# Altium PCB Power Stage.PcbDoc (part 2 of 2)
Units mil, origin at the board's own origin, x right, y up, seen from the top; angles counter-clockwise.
Board outline 9000 x 8000 mil, 6 copper layers (Top Layer, Layer 1, Layer 2, Layer 3, Layer 4, Bottom Layer), stack 92.2 mil thick; 168 components, 72 nets, 534 pads, 347 vias.
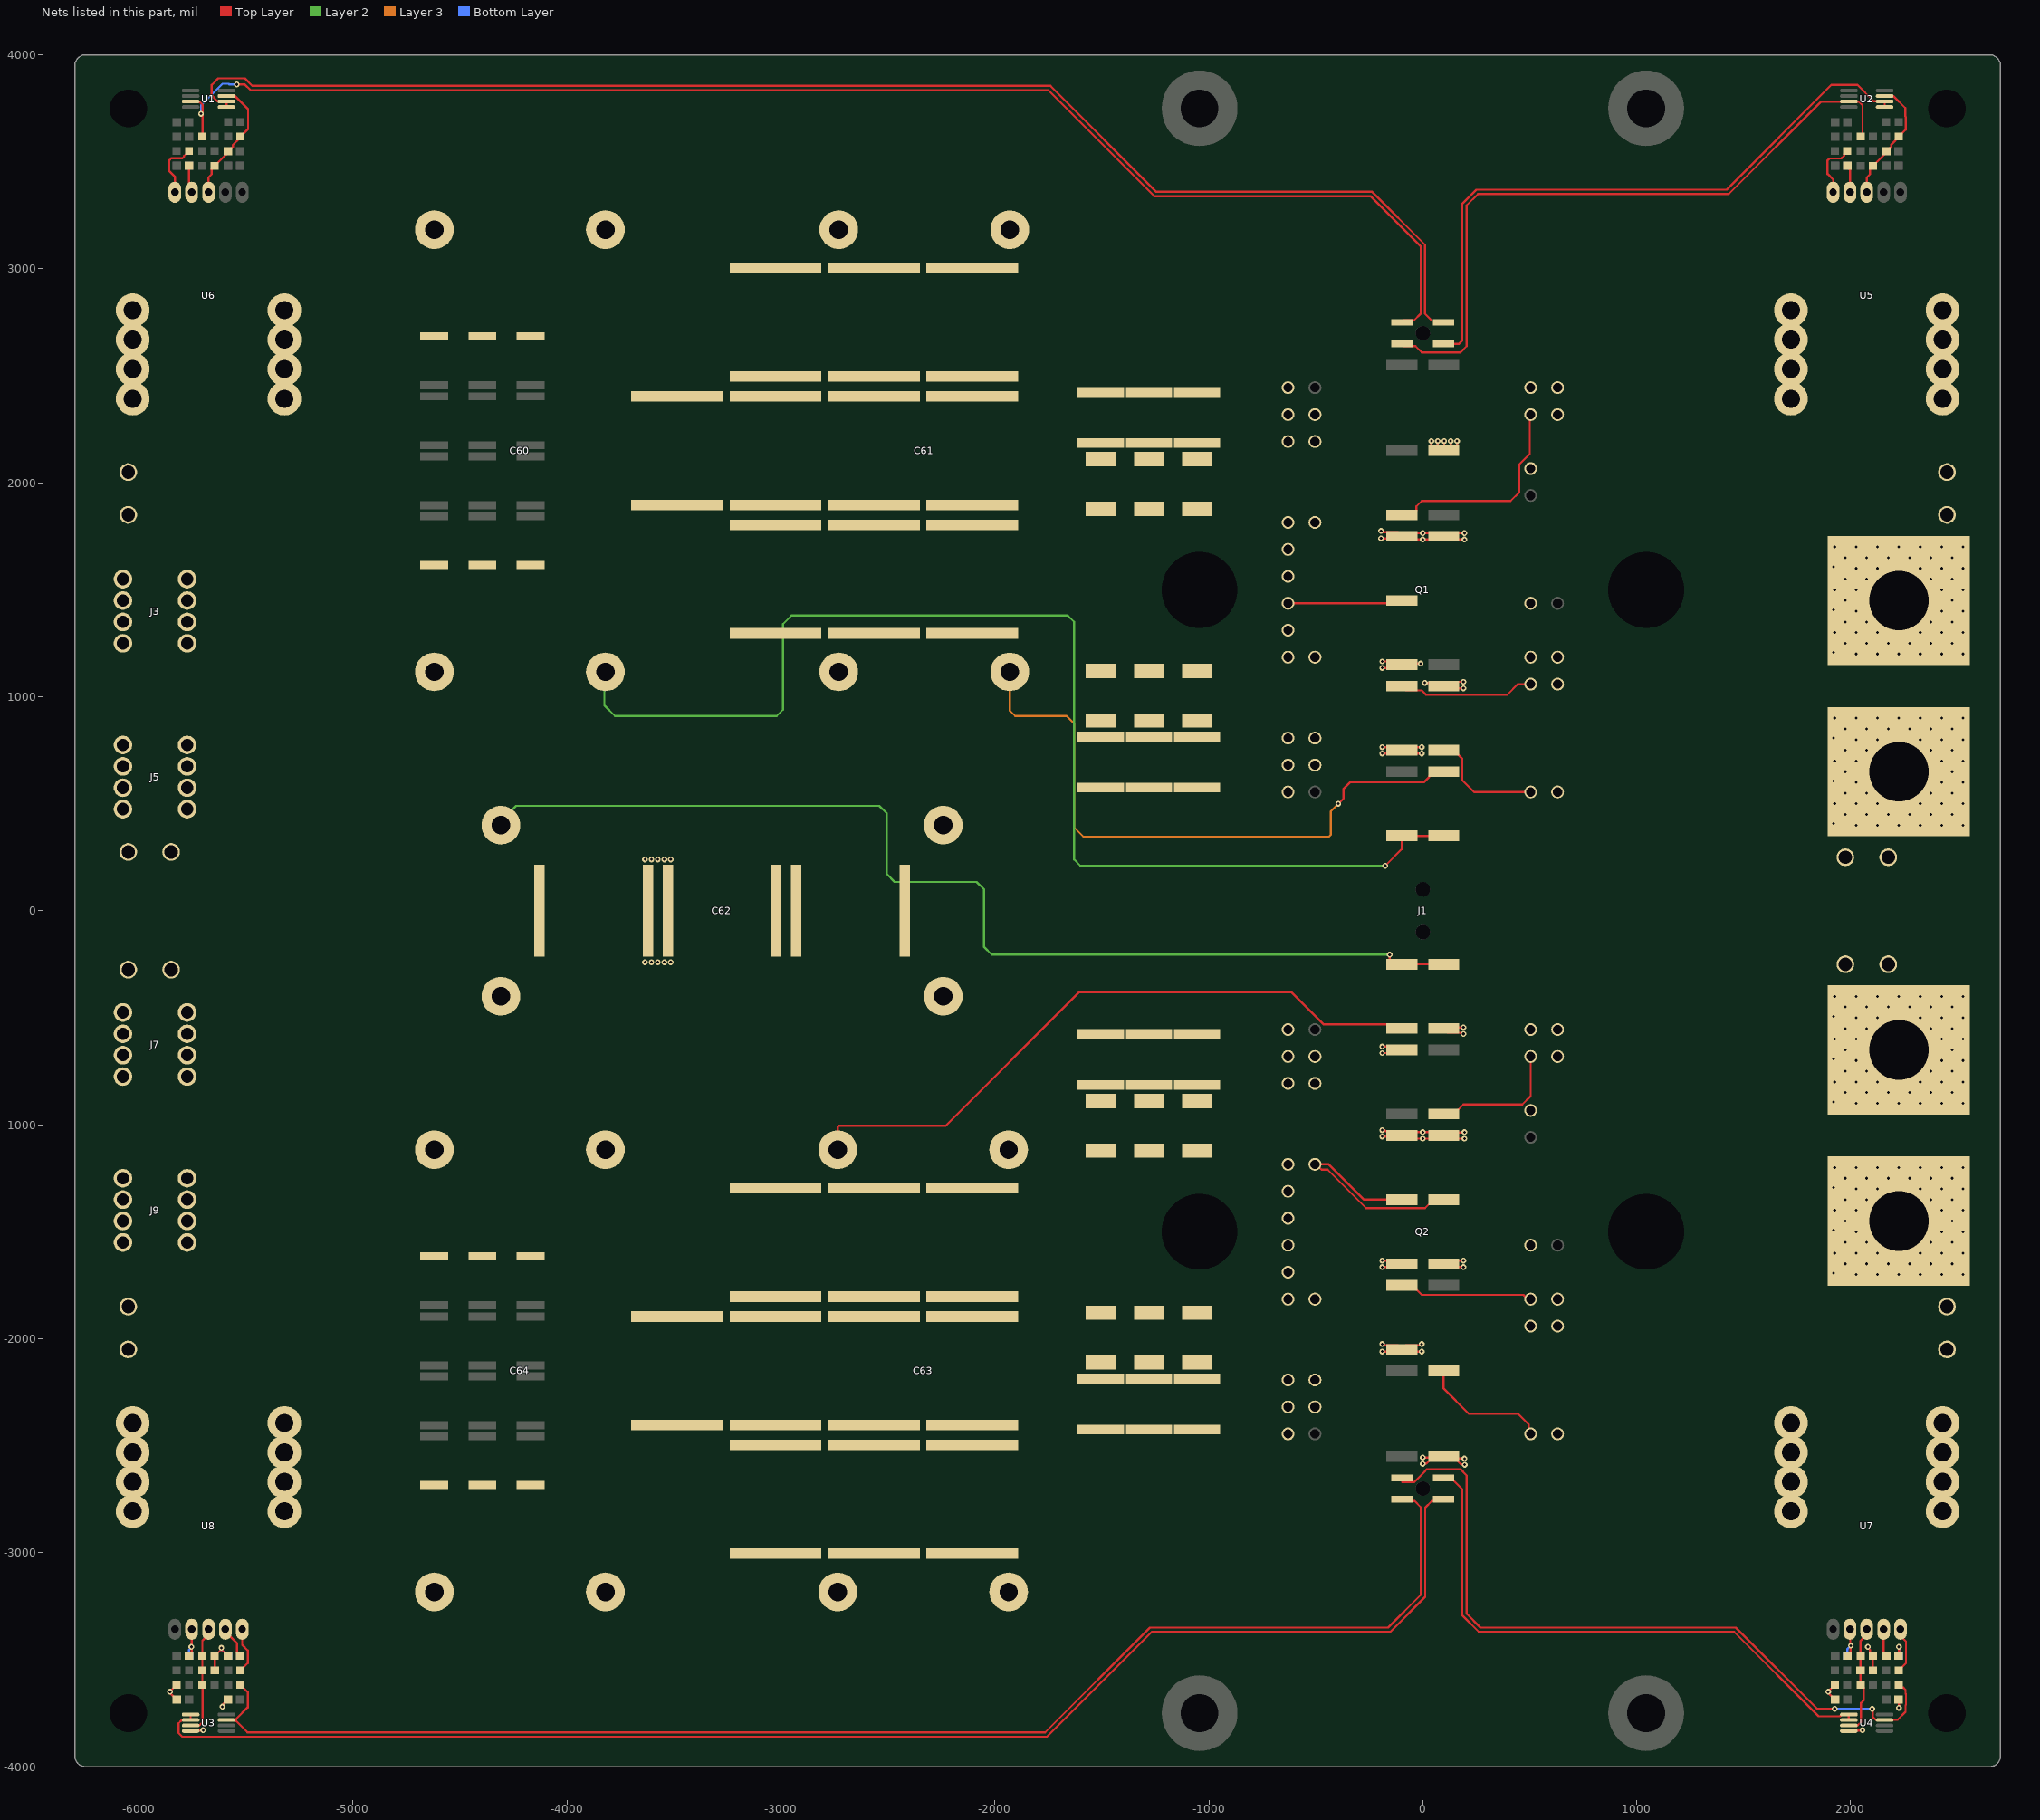
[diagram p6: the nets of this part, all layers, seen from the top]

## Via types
v1: diameter 27, hole 13, Top Layer to Bottom Layer, tented both sides, 347 vias

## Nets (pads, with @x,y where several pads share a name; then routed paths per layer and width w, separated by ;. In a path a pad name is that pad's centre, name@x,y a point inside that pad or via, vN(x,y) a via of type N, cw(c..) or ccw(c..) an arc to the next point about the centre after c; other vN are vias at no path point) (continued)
GND_S: C46.2 C47.2 C48.2 C49.2 C50.2 C51.2 C52.2 C53.2 C54.2 C55.2 C65.2 C66.2 C67.2 C68.2 J1.108 R49.1 R50.1 R55.1 R58.1 U3.4 U4.4 U7.2 U8.2 | length 1529.4
  Top Layer w10: C52.2@-5823.58,-3686 -5824.53,-3686 -5851.75,-3658.78 -5851.75,-3653.25 v1(-5855,-3650) -5855,-3648.47 -5824.53,-3618 R55.1@-5823.62,-3618 ; C46.2@-5766.42,-3482 -5753.74,-3469.32 U8.2@-5753.74,-3357.87 ; U3.4@-5758.66,-3833.39 -5757.18,-3831.91 -5701.91,-3831.91 v1(-5700,-3830) ; C50.2@-5646.42,-3550 -5645.47,-3549.05 -5645.47,-3482 v1@-5618.25,-3454.78 ; v1@-5611.75,-3454.78 -5584.53,-3482 C47.2@-5583.58,-3482 ; v1(-5610,-3720) -5606.75,-3716.75 -5606.75,-3708.22 -5584.53,-3686 C53.2@-5583.58,-3686 ; v1(0,-2585) 1.5,-2583.5 16.5,-2583.5 50,-2550 J1.108@97.44,-2550 107.44,-2560 v1(195,-2560) ; v1(0,-2555) J1.108@87.56,-2555 ; J1.108@145.67,-2554.29 179.17,-2587.79 v1@194.17,-2587.79 ; C54.2@1926.42,-3686 1925.47,-3686 1898.25,-3658.78 1898.25,-3653.25 v1(1895,-3650) 1895,-3648.47 1925.47,-3618 R58.1@1926.38,-3618 ; C48.2@1983.58,-3482 1984.53,-3482 1998.39,-3468.14 1998.39,-3436.61 v1(2000,-3435) 1998.13,-3433.13 1998.13,-3359.74 U7.2@1996.26,-3357.87 ; U4.4@1991.34,-3833.39 1992.82,-3831.91 2053.09,-3831.91 v1(2055,-3830) ; v1(2080,-3440) 2080,-3444.6 2089.76,-3454.36 2089.76,-3469.04 2102.72,-3482 R50.1@2103.62,-3482 R50.1@2103.62,-3482 C51.2@2103.58,-3550 ; C55.2@2223.58,-3686 2225,-3687.42 v1(2225,-3725) ; C49.2@2223.58,-3482 2225,-3480.58 v1(2225,-3440)
  Bottom Layer w10: C68.2@-5766.42,-3482 -5766.42,-3453.71 -5755,-3442.29 v1(-5755,-3440) ; v1(-5615,-3445) -5611.75,-3448.25 -5611.75,-3454.78 -5584.53,-3482 C67.2@-5583.58,-3482 ; C66.2@1983.58,-3482 1983.58,-3451.42 v1(2000,-3435) ; C65.2@2223.58,-3482 2225,-3480.58 v1(2225,-3440)
  other v1: 195.67,-2589.29
IAC+_P: J1.004 U2.1 U2.2 | length 2995.4
  Top Layer w10: J1.004@97.44,2650 169.88,2650 185,2665.12 185,3305 250,3370 1420,3370 1910.41,3860.41 2030.54,3860.41 2107.26,3783.68 2157.18,3783.68 U2.2@2158.66,3782.2 U2.1@2158.66,3756.61
IAC+_S: J1.110 U4.1 U4.2 | length 2729.9
  Top Layer w10: J1.110@97.44,-2650 130.91,-2650 185,-2704.09 185,-3168.28 185,-3293.28 261.72,-3370 1455,-3370 1850,-3765 1949.14,-3765 1957.53,-3756.61 U4.1@1991.34,-3756.61 U4.2@1991.34,-3782.2
IAC-_P: J1.003 R5.1 U2.7 | length 3197.6
  Top Layer w10: J1.003@-97.44,2650 -86.69,2639.25 -34.25,2639.25 -5,2610 176.09,2610 205,2638.91 205,3296.72 258.28,3350 1430,3350 1862.2,3782.2 U2.7@1991.34,3782.2 1992.82,3780.73 2039.27,3780.73 2055,3765 2055,3626.62 R5.1@2046.38,3618
IAC-_S: J1.109 R60.1 U4.7 | length 3423.3
  Top Layer w10: -95,-2670 -40,-2670 10,-2620 10,-2618.79 18.79,-2610 176.09,-2610 205,-2638.9 205,-3285 270,-3350 1463.28,-3350 1843.28,-3730 v1(1925,-3730) ; v1(2100,-3730) 2102.32,-3732.32 2102.32,-3766.5 2116.55,-3780.73 2157.18,-3780.73 U4.7@2158.66,-3782.2 2160.14,-3780.73 2219.27,-3780.73 2256.28,-3743.72 2256.28,-3713.19 2258.39,-3711.08 2258.39,-3660.92 2256.28,-3658.81 2256.28,-3641.28 2245.96,-3630.96 2236.58,-3630.96 R60.1@2223.62,-3618
  Bottom Layer w10: v1(1925,-3730) v1(2100,-3730)
IDC+_P: J1.002 U1.1 U1.2 | length 6526.7
  Top Layer w10: U1.1@-5591.34,3756.61 U1.2@-5591.34,3782.2 -5592.82,3783.68 -5633.45,3783.68 -5660,3810.24 -5660,3860 -5629.61,3890.39 -5505.39,3890.39 -5470,3855 -1740,3855 -1245,3360 -236.72,3360 10,3113.28 10,2790 40.63,2759.37
IDC+_S: J1.112 U3.1 U3.2 | length 6757.6
  Top Layer w10: U3.1@-5758.66,-3756.61 U3.2@-5758.66,-3782.2 -5760.14,-3783.68 -5800.77,-3783.68 -5815,-3797.91 -5815,-3843.27 -5798.27,-3860 -1756.72,-3860 -1266.72,-3370 -152.17,-3370 11.04,-3206.79 11.04,-2789.14 41.69,-2758.49 61.51,-2758.49 70,-2750 J1.112@97.44,-2750
IDC-_P: J1.001 R3.1 U1.7 | length 6727.4
  Top Layer w10: U1.7@-5758.66,3782.2 -5757.18,3780.73 -5716.55,3780.73 -5702.32,3766.5 -5702.32,3619.3 R3.1@-5703.62,3618 ; v1(-5542.84,3861.89) -5542.45,3861.5 -5504.78,3861.5 -5478.28,3835 -1750,3835 -1255,3340 -245,3340 -10,3105 -10,2790 -40.63,2759.37 -88.07,2759.37 J1.001@-97.44,2750
  Bottom Layer w10: v1(-5710,3725) -5710,3765 -5610,3865 -5580.47,3865 -5576.97,3861.5 -5543.22,3861.5 v1(-5542.84,3861.89)
IDC-_S: J1.111 R57.1 U3.7 | length 6545.3
  Top Layer w10: R57.1@-5526.38,-3618 -5525.47,-3618 -5491.61,-3651.86 -5491.61,-3723.11 -5546.57,-3778.06 -5546.57,-3786.35 -5492.91,-3840 -1765,-3840 -1275,-3350 -162.17,-3350 -8.96,-3196.79 -8.96,-2788.06 -37.93,-2759.09 -88.35,-2759.09 J1.111@-97.44,-2750
NTC_P: J1.042 Q1.NTC1 | length 545.7
  Top Layer w10: J1.042@97.44,750 144.88,750 184.88,710 184.88,610.12 239.88,555.12 Q1.NTC1@503.94,555.12
NTC_S: J1.100 Q2.NTC1 | length 599.3
  Top Layer w10: J1.100@97.44,-2150 97.44,-2232.44 215,-2350 445,-2350 494.88,-2399.88 494.88,-2435.83 Q2.NTC1@503.94,-2444.88 Q2.NTC1@504.88,-2443.94
OCD_P_: R7.1 U6.5 | length 283.5
  Top Layer w10: U6.5@-5823.47,3366.88 U6.5@-5832.48,3357.87 -5832.48,3431.01 -5858.39,3456.92 -5858.39,3507.08 -5848.42,3517.04 -5798.55,3517.04 -5789.76,3525.83 -5789.76,3527.52 -5767.28,3550 R7.1@-5766.38,3550
OCD_PB: R9.1 U5.5 | length 272.1
  Top Layer w10: U5.5@1917.52,3357.87 1917.52,3417.48 1891.61,3443.39 1891.61,3507.08 1900.4,3515.86 1956.18,3515.86 1969.76,3529.45 1969.76,3537.04 1977.72,3545 R9.1@1983.62,3545
OCD_S-: R52.1 U8.5 | length 217.8
  Top Layer w10: R52.1@-5526.38,-3550 -5525.47,-3550 -5491.61,-3516.14 -5491.61,-3456.92 -5517.52,-3431.01 U8.5@-5517.52,-3357.87
OCD_SA: R54.1 U7.5 | length 217.8
  Top Layer w10: R54.1@2223.62,-3550 2224.53,-3550 2258.39,-3516.14 2258.39,-3414.62 2232.48,-3388.71 U7.5@2232.48,-3357.87
P+: C11.1 C12.1 C13.1 C17.1 C18.1 C19.1 C20.1 C21.1 C22.1 C23.1 C60.1A C60.1B C61.1A C61.1B J1.027 J1.049 J1.050 J5.1 J5.2 J5.3 J5.4 J5.5 J5.6 J5.7 J5.8 Q1.DC+_1 Q1.DC+_2 Q1.DC+_3 Q1.DC+_4 Q1.DC+_5 Q1.DC+_6 Q1.DC+_7 Q1.DC+_8 R19.2 R20.2 R21.2 R25.2 R26.2 R27.2 R28.2 R29.2 R30.2 TP5.1 TP6.1 | length 6297.3
  Top Layer w10: Q1.DC+_4@-629.92,1437.01 -110.43,1437.01 J1.027@-97.44,1450 ; v1(-176.01,210) -97.44,288.57 J1.049@-97.44,350 J1.050@97.44,350
  Layer 2 w10: C60.1A@-3820.39,1116.54 -3825,1111.93 -3825,960 -3775,910 -3020,910 -2990,940 -2990,1340 -2950,1380 -1660,1380 -1630,1350 -1630,240 -1600,210 v1(-176.01,210)
P-: C11.2 C12.2 C13.2 C14.2 C15.2 C16.2 C17.2 C18.2 C19.2 C20.2 C21.2 C22.2 C23.2 C24.2 C25.2 C26.2 C60.2A C60.2B C61.2A C61.2B J1.044 Q1.DC-1_1 Q1.DC-1_2 Q1.DC-1_3 Q1.DC-1_4 Q1.DC-2_1 Q1.DC-2_2 Q1.DC-2_3 Q1.DC-2_4 R13.1 R14.1 R15.1 U6.6 U6.7 U6.8 U6.9 | length 2957.7
  Top Layer w10: v1(-395,500) -370,525 -370,570 -340,600 5,600 30,625 30,630 50,650 J1.044@97.44,650
  Layer 3 w10: C61.2B@-1930.39,1116.54 -1930.39,935.39 -1905,910 -1665,910 -1630,875 -1630,390 -1585,345 -440,345 -430,355 -430,465 v1(-395,500)
P-_IO: J3.1 J3.2 J3.3 J3.4 J3.5 J3.6 J3.7 J3.8 TP1.1 TP3.1 U6.10 U6.11 U6.12 U6.13
PA: J1.035 J4.1 Q1.AC1_1 Q1.AC1_2 Q1.AC1_3 Q1.AC1_4 TP7.1 TP8.1 | length 638.3
  Top Layer w10: J1.035@-97.44,1050 -77.44,1030 -5,1030 15,1010 395,1010 444.06,1059.06 Q1.AC1_2@503.94,1059.06
  other v1: 2025,400 2125,400 2225,400 2325,400 2425,400 2525,400 1919.41,406.91 1975,450 2075,450 2175,450 2275,450 2375,450 2475,450 1925,500 2025,500 2125,500 2325,500 2425,500 2525,500 1975,550 2075,550 2375,550 2475,550 2025,600 2425,600 2525,600 1919.41,606.91 1975,650 2475,650 1925,700 2025,700 2425,700 2525,700 1975,750 2075,750 2375,750 2475,750 2025,800 2125,800 2325,800 2425,800 2525,800 1919.41,806.91 1975,850 2075,850 2175,850 2275,850 2375,850 2475,850 1925,900 2025,900 2125,900 2225,900 2325,900 2425,900 2525,900
PB: J1.019 Q1.AC2_1 Q1.AC2_2 Q1.AC2_3 Q1.AC2_4 U5.6 U5.7 U5.8 U5.9 | length 988.9
  Top Layer w10: J1.019@-97.44,1850 -50,1850 -30,1870 -30,1890 -5,1915 410,1915 450,1955 450,2085 500,2135 500,2314.96 Q1.AC2_2@503.94,2318.9
PB_IO: J2.1 TP2.1 TP4.1 U5.10 U5.11 U5.12 U5.13
  other v1: 2025,1200 2125,1200 2225,1200 2325,1200 2425,1200 2525,1200 1919.41,1206.91 1975,1250 2075,1250 2175,1250 2275,1250 2375,1250 2475,1250 1925,1300 2025,1300 2125,1300 2325,1300 2425,1300 2525,1300 1975,1350 2075,1350 2375,1350 2475,1350 2025,1400 2425,1400 2525,1400 1919.41,1406.91 1975,1450 2475,1450 1925,1500 2025,1500 2425,1500 2525,1500 1975,1550 2075,1550 2375,1550 2475,1550 2025,1600 2125,1600 2325,1600 2425,1600 2525,1600 1919.41,1606.91 1975,1650 2075,1650 2175,1650 2275,1650 2375,1650 2475,1650 1925,1700 2025,1700 2125,1700 2225,1700 2325,1700 2425,1700 2525,1700
S1_P: J1.033 J1.036 Q1.S1 | length 578.3
  Top Layer w10: v1(-190,1135) -112.44,1135 J1.033@-97.44,1150 ; v1(-190,1165) -112.44,1165 J1.033@-97.44,1150 ; v1(-10,1155) -92.44,1155 J1.033@-97.44,1150 ; v1(10,1065) 82.44,1065 J1.036@97.44,1050 ; v1(190,1040) 107.44,1040 J1.036@97.44,1050 ; v1(190,1070) 117.44,1070 J1.036@97.44,1050
S1_S: J1.089 J1.090 Q2.S1 | length 352.7
  Top Layer w10: v1(-190,-1665) J1.089@-112.44,-1665 ; v1(-190,-1635) J1.089@-112.44,-1635 ; v1(190,-1665) 112.44,-1665 J1.090@97.44,-1650 112.44,-1635 v1(190,-1635)
S2_P: J1.041 Q1.NTC2 Q1.S2 | length 394.9
  Top Layer w10: v1(-190,735) -112.44,735 J1.041@-97.44,750 ; v1(-190,765) -112.44,765 J1.041@-97.44,750 ; v1(-5,735) -82.44,735 J1.041@-97.44,750 ; v1(-5,765) -82.44,765 J1.041@-97.44,750
S2_S: J1.097 Q2.NTC2 Q2.S2 | length 399
  Top Layer w10: v1(-190,-2060) -107.44,-2060 J1.097@-97.44,-2050 ; v1(-190,-2025) -185.4,-2025 -180.4,-2030 -117.44,-2030 J1.097@-97.44,-2050 ; v1(-5,-2060) -87.44,-2060 J1.097@-97.44,-2050 ; v1(-5,-2025) -9.6,-2025 -14.6,-2030 -77.44,-2030 J1.097@-97.44,-2050
S3_P: J1.021 J1.022 Q1.S3 | length 810.6
  Top Layer w10: v1(-195,1740) -107.44,1740 J1.021@-97.44,1750 ; v1(-195,1775) -190.4,1775 -185.4,1770 -117.44,1770 J1.021@-97.44,1750 ; J1.022@82.44,1735 v1(0,1735) -82.44,1735 J1.021@-97.44,1750 ; v1(195,1735) 112.44,1735 J1.022@97.44,1750 ; v1(195,1765) 112.44,1765 J1.022@97.44,1750 ; J1.021@-97.44,1750 -82.44,1765 v1(0,1765) 82.44,1765 J1.022@97.44,1750
S3_S: J1.077 J1.078 Q2.S3 | length 798.5
  Top Layer w10: v1(-190,-1055) -102.44,-1055 J1.077@-97.44,-1050 ; v1(-190,-1025) -188.5,-1026.5 -178.19,-1026.5 -174.69,-1030 -117.44,-1030 J1.077@-97.44,-1050 ; J1.077@-82.44,-1065 v1(0,-1065) 82.44,-1065 J1.078@97.44,-1050 ; v1(195,-1065) 112.44,-1065 J1.078@97.44,-1050 ; v1(195,-1035) 194.02,-1035.98 111.46,-1035.98 J1.078@97.44,-1050 ; J1.077@-97.44,-1050 -82.44,-1035 v1(0,-1035) 82.44,-1035 J1.078@97.44,-1050
S4_P: J1.014 Q1.S4 | length 236.6
  Top Layer w10: v1(40,2195) 40,2160 50,2150 J1.014@97.44,2150 ; J1.014@60,2170 70,2170 v1(70,2195) ; J1.014@90,2170 100,2170 v1(100,2195) ; J1.014@120,2170 130,2170 v1(130,2195) ; J1.014@150,2170 160,2170 v1(160,2195)
S4_S: J1.068 J1.069 Q2.S4 | length 395.1
  Top Layer w10: v1(-190,-665) -112.44,-665 J1.069@-97.44,-650 -112.44,-635 v1(-190,-635) ; v1(190,-575) 186.75,-571.75 176.44,-571.75 174.69,-570 117.44,-570 J1.068@97.44,-550 102.44,-545 v1(190,-545)
S+: C27.1 C28.1 C29.1 C33.1 C34.1 C35.1 C36.1 C37.1 C38.1 C39.1 C43.1 C44.1 C45.1 C62.1A C62.1B C63.1A C63.1B C64.1A C64.1B J1.061 J1.062 J1.083 J1.084 J7.1 J7.2 J7.3 J7.4 J7.5 J7.6 J7.7 J7.8 Q2.DC+_1 Q2.DC+_2 Q2.DC+_3 Q2.DC+_4 Q2.DC+_5 Q2.DC+_6 Q2.DC+_7 Q2.DC+_8 R31.2 R32.2 R33.2 R34.2 R35.2 R36.2 R37.2 R38.2 R39.2 TP11.1 TP12.1 | length 6278.1
  Top Layer w10: v1(-155,-205) -155,-230 -135,-250 J1.061@-97.44,-250 J1.062@97.44,-250 ; J1.083@-97.44,-1350 -275.08,-1350 -440.04,-1185.04 Q2.DC+_7@-503.94,-1185.04 -498.5,-1185.04 -473.54,-1210 -445,-1210 -265,-1390 10,-1390 50,-1350 J1.084@97.44,-1350
  Layer 2 w10: C62.1B@-4308.46,399.61 -4308.46,419.7 -4238.16,490 -2540,490 -2505,455 -2505,171.63 -2468.37,135 -2085,135 -2050,100 -2050,-170 -2015,-205 v1(-155,-205)
S-: C27.2 C28.2 C29.2 C30.2 C31.2 C32.2 C33.2 C34.2 C35.2 C36.2 C37.2 C38.2 C39.2 C40.2 C41.2 C42.2 C43.2 C44.2 C45.2 C62.2A C62.2B C63.2A C63.2B C64.2A C64.2B J1.067 Q2.DC-1_1 Q2.DC-1_2 Q2.DC-1_3 Q2.DC-1_4 Q2.DC-2_1 Q2.DC-2_2 Q2.DC-2_3 Q2.DC-2_4 R46.1 R47.1 R48.1 U8.10 U8.11 U8.12 U8.13 | length 3120.9
  Top Layer w10: C63.2B@-2734.61,-1116.54 -2734.61,-1010.86 -2728.75,-1005 -2230,-1005 -1605,-380 -615,-380 -465,-530 -117.44,-530 J1.067@-97.44,-550 ; C62.2A@-2241.54,-399.61 C62.2A@-2208.8,-366.87
  other v1: -3635,-240 -3605,-240 -3575,-240 -3545,-240 -3515,-240 -3635,240 -3605,240 -3575,240 -3545,240 -3515,240
S-_IO: J9.1 J9.2 J9.3 J9.4 J9.5 J9.6 J9.7 J9.8 TP13.1 TP15.1 U8.6 U8.7 U8.8 U8.9
SA: J1.091 Q2.AC1_1 Q2.AC1_2 Q2.AC1_3 Q2.AC1_4 U7.6 U7.7 U7.8 U7.9 | length 628.3
  Top Layer w10: J1.091@-97.44,-1750 -50,-1750 -5,-1795 470.45,-1795 490.41,-1814.96 Q2.AC1_1@503.94,-1814.96
SA_IO: J8.1 TP14.1 TP16.1 U7.10 U7.11 U7.12 U7.13
  other v1: 2025,-1700 2125,-1700 2225,-1700 2325,-1700 2425,-1700 2525,-1700 1919.41,-1693.09 1975,-1650 2075,-1650 2175,-1650 2275,-1650 2375,-1650 2475,-1650 1925,-1600 2025,-1600 2125,-1600 2325,-1600 2425,-1600 2525,-1600 1975,-1550 2075,-1550 2375,-1550 2475,-1550 2025,-1500 2425,-1500 2525,-1500 1919.41,-1493.09 1975,-1450 2475,-1450 1925,-1400 2025,-1400 2425,-1400 2525,-1400 1975,-1350 2075,-1350 2375,-1350 2475,-1350 2025,-1300 2125,-1300 2325,-1300 2425,-1300 2525,-1300 1919.41,-1293.09 1975,-1250 2075,-1250 2175,-1250 2275,-1250 2375,-1250 2475,-1250 1925,-1200 2025,-1200 2125,-1200 2225,-1200 2325,-1200 2425,-1200 2525,-1200
SB: J1.076 J6.1 Q2.AC2_1 Q2.AC2_2 Q2.AC2_3 Q2.AC2_4 TP9.1 TP10.1 | length 626.2
  Top Layer w10: J1.076@97.44,-950 144.88,-950 189.88,-905 465,-905 503.94,-866.06 Q2.AC2_2@503.94,-681.1
  other v1: 2025,-900 2125,-900 2225,-900 2325,-900 2425,-900 2525,-900 1919.41,-893.09 1975,-850 2075,-850 2175,-850 2275,-850 2375,-850 2475,-850 1925,-800 2025,-800 2125,-800 2325,-800 2425,-800 2525,-800 1975,-750 2075,-750 2375,-750 2475,-750 2025,-700 2425,-700 2525,-700 1919.41,-693.09 1975,-650 2475,-650 1925,-600 2025,-600 2425,-600 2525,-600 1975,-550 2075,-550 2375,-550 2475,-550 2025,-500 2125,-500 2325,-500 2425,-500 2525,-500 1919.41,-493.09 1975,-450 2075,-450 2175,-450 2275,-450 2375,-450 2475,-450 1925,-400 2025,-400 2125,-400 2225,-400 2325,-400 2425,-400 2525,-400
SNBP0: C24.1 C25.1 C26.1 R28.1 R29.1 R30.1
SNBP1: C14.1 C15.1 C16.1 R19.1 R20.1 R21.1
SNBS0: C30.1 C31.1 C32.1 R31.1 R32.1 R33.1
SNBS1: C40.1 C41.1 C42.1 R37.1 R38.1 R39.1
VO_P-: C5.1 R4.2 R11.2 U1.3 U6.3 | length 594.5
  Top Layer w10: U6.3@-5675,3357.87 -5675,3427.25 -5660.24,3442.01 -5660.24,3469.04 -5647.28,3482 R11.2@-5646.38,3482 -5645.47,3482 -5593.39,3534.08 -5593.39,3536.14 -5579.53,3550 -5579.53,3553.1 -5568.76,3563.86 -5567.09,3563.86 -5561.24,3569.72 -5561.24,3579.05 -5540.24,3600.04 -5540.24,3605.04 -5527.28,3618 R4.2@-5526.38,3618 ; U1.3@-5591.34,3807.8 -5589.86,3806.32 -5549.23,3806.32 -5490,3747.09 -5490,3653.47 R4.2@-5525.47,3618
VO_PB: C6.1 R6.2 R12.2 U2.3 U5.3 | length 592.4
  Top Layer w10: U5.3@2075,3357.87 2075,3427.25 2089.76,3442.01 2089.76,3469.04 2102.72,3482 R12.2@2103.62,3482 2104.53,3482 2156.61,3534.08 2156.61,3536.14 2170.47,3550 2170.47,3553.1 2181.24,3563.86 2182.91,3563.86 2188.76,3569.72 2188.76,3579.05 2209.76,3600.04 2209.76,3605.04 2222.72,3618 R6.2@2223.62,3618 ; U2.3@2158.66,3807.8 2160.14,3806.32 2200.77,3806.32 2255,3752.09 2255,3712.65 2257.48,3710.17 2257.48,3650.96 R6.2@2224.53,3618
VO_S-: C50.1 R49.2 R56.2 U3.3 U8.3 | length 509.5
  Top Layer w10: U3.3@-5758.66,-3807.8 -5757.18,-3806.32 -5716.55,-3806.32 -5702.32,-3792.09 -5702.32,-3619.3 R56.2@-5703.62,-3618 C50.1@-5703.58,-3550 C50.1@-5703.58,-3550 R49.2@-5703.62,-3482 R49.2@-5703.62,-3482 -5703.62,-3411.91 -5675,-3383.29 U8.3@-5675,-3357.87
VO_SA: C51.1 R50.2 R59.2 U4.3 U7.3 | length 520.1
  Top Layer w10: U4.3@1991.34,-3807.8 1992.82,-3806.32 2033.45,-3806.32 2047.68,-3792.09 2047.68,-3702.97 2060,-3690.65 2060,-3630.96 2047.04,-3618 R59.2@2046.38,-3618 R59.2@2046.38,-3618 C51.1@2046.42,-3550 R50.2@2046.38,-3482 R50.2@2046.38,-3482 2046.38,-3411.91 2075,-3383.29 U7.3@2075,-3357.87
VREF_P-: C7.1 U6.4 | length 129.4
  Top Layer w10: C7.1@-5766.42,3482 -5766.42,3403.52 -5753.74,3390.83 U6.4@-5753.74,3357.87
VREF_PB: C9.1 U5.4 | length 124.4
  Top Layer w10: C9.1@1983.58,3477 1996.26,3464.32 U5.4@1996.26,3357.87
VREF_S-: C47.1 U8.4 | length 153.6
  Top Layer w10: U8.4@-5596.26,-3357.87 -5596.26,-3368.74 -5541.24,-3423.76 -5541.24,-3468.14 -5527.37,-3482 C47.1@-5526.42,-3482
VREF_SA: C49.1 U7.4 | length 129.4
  Top Layer w10: U7.4@2153.74,-3357.87 2153.74,-3469.32 C49.1@2166.42,-3482
pads on no net: HS1.1 HS1.2 HS1.3 HS1.4 J1. MH1.1 MH2.1 MH3.1 MH4.1 Q1.MH1 Q1.MH2 Q2.MH1 Q2.MH2

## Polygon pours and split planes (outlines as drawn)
G4_P on Top Layer "Top Layer-G4_P" (solid, pour order 683): 17 vertices, not listed, extent -545,2100 215,2485.15
G3_P on Top Layer "Top Layer-G3_P" (solid, pour order 666): 525.1,1690 ccw(c525,1740) 575,1740 575,2070.1 ccw(c525,2070) 525,2120 489.9,2120 ccw(c490,2070) 440,2070 440,1975 cw(c390,1975) 390.1,1925 -160.1,1925 ccw(c-160,1875) -210,1875 -210,1739.9 ccw(c-160,1740) -160,1690
G1_P on Top Layer "Top Layer-G1_P" (solid, pour order 655): 17 vertices, not listed, extent -210,990 680,1490
G3_S on Top Layer "Top Layer-G3_S" (solid, pour order 626): 500.1,-1090 ccw(c500,-1040) 550,-1040 550,-949.9 ccw(c500,-950) 500,-900 -160,-900 ccw(c-160,-950) -210,-949.9 -210,-1040 ccw(c-159.95,-1039.95) -160,-1090
G1_S on Top Layer "Top Layer-G1_S" (solid, pour order 557): 435,-1750 cw(c485.05,-1750.05) 485.05,-1700 624.5,-1700 ccw(c625,-1650) 675,-1650 675,-1545 ccw(c624.95,-1545.05) 625,-1495 380,-1495 ccw(c380.04,-1545.04) 330,-1545 cw(c280,-1545) 280.1,-1595 -160.1,-1595 ccw(c-160,-1645) -210,-1645 -210,-1750.1 ccw(c-160,-1750) -160,-1800 385.1,-1800 ccw(c385,-1750)
G4_S on Top Layer "Top Layer-G4_S" (solid, pour order 503): -585,-660 ccw(c-535,-660) -534.98,-710 170.03,-710 ccw(c170,-660) 220,-660.09 220,-569.88 ccw(c170,-570) 170,-520 -535.1,-520 ccw(c-535,-570) -585,-570
G2_S on Top Layer "Top Layer-G2_S" (solid, pour order 610): 17 vertices, not listed, extent -545,-2475 5,-2085
P- on Top Layer "Top Layer-P- 1" (solid, pour order 934): 17 vertices, not listed, extent -1630,395 -450,865
SA_IO on Top Layer "Top Layer-SA_IO" (solid, pour order 69): 2600,-2875 cw(c2550,-2875) 2550,-2925 1649.9,-2925 cw(c1650,-2875) 1600,-2875 1600,-1194.9 cw(c1649.95,-1194.95) 1649.9,-1145 2550,-1145 cw(c2549.95,-1195.05) 2600,-1195
P- on Top Layer "Top Layer-P- 2" (solid, pour order 903): 18 vertices, not listed, extent -3740,2135 -450,2620
S- on Top Layer "Top Layer-S- 2" (solid, pour order 899): 18 vertices, not listed, extent -3740,-2620 -450,-2135
P+ on Top Layer "Top Layer-P+" (solid, pour order 894): 31 vertices, not listed, extent -6200,200 -450,1965
G2_P on Top Layer "Top Layer-G2_P" (solid, pour order 710): -585,569.9 ccw(c-535,570) -535,520 -434.9,520 ccw(c-435,570) -385,570 -384.75,570 cw(c-335,565) -335.1,615 -40,615 ccw(c-40.05,665.05) 9.94,662.53 ccw(c-40,660) -40,710 -535.1,710 ccw(c-535,660) -585,660
S+ on Top Layer "Top Layer-S+" (solid, pour order 822): 42 vertices, not listed, extent -6200,-1930 -450,500
SB on Top Layer "Top Layer-SB" (solid, pour order 814): 17 vertices, not listed, extent 450,-955 2600,-200
PA on Top Layer "Top Layer-PA" (solid, pour order 808): 22 vertices, not listed, extent 450,200 2599.9,1250
SNBP1 on Top Layer "Top Layer-SNBS0" (solid, pour order 793): -1455,2075 -980,2075 ccw(c-980.05,2125.05) -930,2125 -930,2175 ccw(c-980.04,2174.96) -980,2225 -1580,2225 ccw(c-1579.98,2174.98) -1630,2175 -1630,2125 ccw(c-1579.95,2125.05) -1580,2075
SNBP0 on Top Layer "Top Layer-SNBS0" (solid, pour order 792): -1455,925 -980,925 cw(c-980.05,874.95) -930,875 -930,825 cw(c-980.04,825.04) -980,775 -1580,775 cw(c-1579.98,825.02) -1630,825 -1630,875 cw(c-1579.95,874.95) -1580,925
SNBS1 on Top Layer "Top Layer-SNBS0" (solid, pour order 791): -1455,-2075 -980,-2075 cw(c-980.05,-2125.05) -930,-2125 -930,-2175 cw(c-980.04,-2174.96) -980,-2225 -1580,-2225 cw(c-1579.98,-2174.98) -1630,-2175 -1630,-2125 cw(c-1579.95,-2125.05) -1580,-2075
SNBS0 on Top Layer "Top Layer-SNBS0" (solid, pour order 477): -1455,-925 -980,-925 ccw(c-980.05,-874.95) -930,-875 -930,-825 ccw(c-980.04,-825.04) -980,-775 -1580,-775 ccw(c-1579.98,-825.02) -1630,-825 -1630,-875 ccw(c-1579.95,-874.95) -1580,-925
P- on Top Layer "Top Layer-S- 3" (solid, pour order 761): -1850,1340 cw(c-1850,1290) -1800,1290 -1800.1,1069.9 cw(c-1850.14,1070.03) -1850,1020 -3210,1020 cw(c-3210,1070) -3260,1069.9 -3260,1290 cw(c-3210,1290) -3210.1,1340
P+ on Top Layer "Top Layer-S- 3" (solid, pour order 790): -1850.39,2959.61 ccw(c-1850.39,3009.6) -1800.39,3009.61 -1800.49,3229.71 ccw(c-1850.53,3229.57) -1850.39,3279.61 -3210.39,3279.61 ccw(c-3210.4,3229.61) -3260.39,3229.71 -3260.39,3009.61 ccw(c-3210.39,3009.61) -3210.49,2959.61
S+ on Top Layer "Top Layer-S- 3" (solid, pour order 789): -1855.39,-2959.61 cw(c-1855.39,-3009.6) -1805.39,-3009.61 -1805.49,-3229.71 cw(c-1855.53,-3229.57) -1855.39,-3279.61 -3215.39,-3279.61 cw(c-3215.4,-3229.61) -3265.39,-3229.71 -3265.39,-3009.61 cw(c-3215.39,-3009.61) -3215.49,-2959.61
S- on Top Layer "Top Layer-S- 3" (solid, pour order 788): -1855.39,-1340.39 ccw(c-1855.39,-1290.4) -1805.39,-1290.39 -1805.49,-1070.29 ccw(c-1855.53,-1070.43) -1855.39,-1020.39 -3215.39,-1020.39 ccw(c-3215.4,-1070.39) -3265.39,-1070.29 -3265.39,-1290.39 ccw(c-3215.39,-1290.39) -3215.49,-1340.39
S- on Top Layer "Top Layer-S- 1" (solid, pour order 512): 17 vertices, not listed, extent -1630,-865 -450,-395
PB_IO on Top Layer "Top Layer-PB_IO" (solid, pour order 72): 2600,2875 ccw(c2550,2875) 2550,2925 1649.9,2925 ccw(c1650,2875) 1600,2875 1600,1194.9 ccw(c1649.95,1194.95) 1649.9,1145 2550,1145 ccw(c2549.95,1195.05) 2600,1195
S-_IO on Top Layer "Top Layer-S-_IO" (solid, pour order 166): -6200,-1195 cw(c-6149.95,-1195.05) -6150,-1145 -5684.83,-1145 cw(c-5685,-1195) -5635,-1195 -5635,-1960 ccw(c-5585,-1960) -5585.1,-2010 -5249.9,-2010 cw(c-5250,-2060) -5200,-2059.83 -5200,-2875 cw(c-5250,-2875) -5249.9,-2925 -6150,-2925 cw(c-6150,-2875) -6200,-2875
P-_IO on Top Layer "Top Layer-P-_IO" (solid, pour order 165): -6200,1195 ccw(c-6149.95,1195.05) -6150,1145 -5684.83,1145 ccw(c-5685,1195) -5635,1195 -5635,1960 cw(c-5585,1960) -5585.1,2010 -5249.9,2010 ccw(c-5250,2060) -5200,2059.83 -5200,2875 ccw(c-5250,2875) -5249.9,2925 -6150,2925 ccw(c-6150,2875) -6200,2875
S- on Top Layer "Top Layer-S-" (solid, pour order 403): -2410,-500 -2089.9,-500 ccw(c-2090,-450) -2040,-450 -2040,450.1 ccw(c-2090,450) -2090,500 -2410.1,500 ccw(c-2410,450) -2460,450 -2460,-450.1 ccw(c-2410,-450)
S- on Top Layer "Top Layer-S- 4" (solid, pour order 417): -3610,-280 -3540,-280 ccw(c-3540.05,-229.95) -3490,-230 -3490,450 ccw(c-3540.05,449.95) -3540,500 -3610,500 ccw(c-3609.96,449.96) -3660,450 -3660,-230 ccw(c-3609.95,-229.95)
BLDP0 on Top Layer "Top Layer-BLDP0" (solid, pour order 387): -4710,1864.9 ccw(c-4660,1865) -4660,1815 -4129.9,1815 ccw(c-4130,1865) -4080,1865 -4080,1875.1 ccw(c-4130,1875) -4130,1925 -4660.1,1925 ccw(c-4660,1875) -4710,1875
BLDP1 on Top Layer "Top Layer-BLDP1" (solid, pour order 388): -4710,2144.9 ccw(c-4660,2145) -4660,2095 -4129.9,2095 ccw(c-4130,2145) -4080,2145 -4080,2155.1 ccw(c-4130,2155) -4130,2205 -4660.1,2205 ccw(c-4660,2155) -4710,2155
BLDP2 on Top Layer "Top Layer-BLDP2" (solid, pour order 389): -4710,2424.9 ccw(c-4660,2425) -4660,2375 -4129.9,2375 ccw(c-4130,2425) -4080,2425 -4080,2435.1 ccw(c-4130,2435) -4130,2485 -4660.1,2485 ccw(c-4660,2435) -4710,2435
BLDS0 on Top Layer "Top Layer-BLDS0" (solid, pour order 390): -4710,-1875.1 ccw(c-4660,-1875) -4660,-1925 -4129.9,-1925 ccw(c-4130,-1875) -4080,-1875 -4080,-1864.9 ccw(c-4130,-1865) -4130,-1815 -4660.1,-1815 ccw(c-4660,-1865) -4710,-1865
BLDS1 on Top Layer "Top Layer-BLDS1" (solid, pour order 391): -4710,-2155.1 ccw(c-4660,-2155) -4660,-2205 -4129.9,-2205 ccw(c-4130,-2155) -4080,-2155 -4080,-2144.9 ccw(c-4130,-2145) -4130,-2095 -4660.1,-2095 ccw(c-4660,-2145) -4710,-2145
BLDS2 on Top Layer "Top Layer-BLDS2" (solid, pour order 392): -4710,-2435.1 ccw(c-4660,-2435) -4660,-2485 -4129.9,-2485 ccw(c-4130,-2435) -4080,-2435 -4080,-2424.9 ccw(c-4130,-2425) -4130,-2375 -4660.1,-2375 ccw(c-4660,-2425) -4710,-2425
S- on Top Layer "Top Layer-S- 5" (solid, pour order 411): -3779.9,-3280 ccw(c-3780,-3230) -3730,-3230 -3730,-3029.9 ccw(c-3780,-3030) -3780,-2980 -4030,-2980 cw(c-4030,-2930) -4080,-2930 -4080,-2704.89 ccw(c-4130,-2705) -4130,-2655 -4660.1,-2655 ccw(c-4660.01,-2704.99) -4710,-2705 -4710,-3230 ccw(c-4660,-3230) -4660,-3280
P- on Top Layer "Top Layer-P-" (solid, pour order 412): -3779.9,3280 cw(c-3780,3230) -3730,3230 -3730,3029.9 cw(c-3780,3030) -3780,2980 -4030,2980 ccw(c-4030,2930) -4080,2930 -4080,2704.89 cw(c-4130,2705) -4130,2655 -4660.1,2655 cw(c-4660.01,2704.99) -4710,2705 -4710,3230 cw(c-4660,3230) -4660,3280
S+ on Layer 2 "Layer 2-S+" (solid, pour order 859): 47 vertices, not listed, extent -6200,-3280 -450,475
+5V_P on Layer 2 "Layer 1-GND_S" (solid, pour order 940): 27 vertices, not listed, extent -5880,2520 2274.9,3900
+5V_S on Layer 2 "Layer 1-GND_S" (solid, pour order 935): 27 vertices, not listed, extent -5880,-3900 2274.9,-2520
SA_IO on Layer 2 "Top Layer-SA_IO" (solid, pour order 925): 2600,-2875 cw(c2550,-2875) 2550,-2925 1649.9,-2925 cw(c1650,-2875) 1600,-2875 1600,-1194.9 cw(c1649.95,-1194.95) 1649.9,-1145 2550,-1145 cw(c2549.95,-1195.05) 2600,-1195
SB on Layer 2 "Layer 2-SB" (solid, pour order 911): 17 vertices, not listed, extent 450,-955 2600,-200
PA on Layer 2 "Layer 2-PA" (solid, pour order 910): 22 vertices, not listed, extent 450,200 2599.9,1250
PB_IO on Layer 2 "Top Layer-PB_IO" (solid, pour order 904): 2600,2875 ccw(c2550,2875) 2550,2925 1649.9,2925 ccw(c1650,2875) 1600,2875 1600,1194.9 ccw(c1649.95,1194.95) 1649.9,1145 2550,1145 ccw(c2549.95,1195.05) 2600,1195
P+ on Layer 2 "Layer 2-P+" (solid, pour order 870): 51 vertices, not listed, extent -6200,200 -450,3280
P-_IO on Layer 2 "Layer 2-P-_IO" (solid, pour order 346): -6200,1195 ccw(c-6149.95,1195.05) -6150,1145 -5684.83,1145 ccw(c-5685,1195) -5635,1195 -5635,1960 cw(c-5585,1960) -5585.1,2010 -5249.9,2010 ccw(c-5250,2060) -5200,2059.83 -5200,2875 ccw(c-5250,2875) -5249.9,2925 -6150,2925 ccw(c-6150,2875) -6200,2875
S-_IO on Layer 2 "Layer 2-S-_IO" (solid, pour order 341): -6200,-1195 cw(c-6149.95,-1195.05) -6150,-1145 -5684.83,-1145 cw(c-5685,-1195) -5635,-1195 -5635,-1960 ccw(c-5585,-1960) -5585.1,-2010 -5249.9,-2010 cw(c-5250,-2060) -5200,-2059.83 -5200,-2875 cw(c-5250,-2875) -5249.9,-2925 -6150,-2925 cw(c-6150,-2875) -6200,-2875
S- on Layer 1 "Layer 1-S-" (solid, pour order 853): 69 vertices, not listed, extent -6200,-3280 -450,500
GND_P on Layer 1 "Layer 1-GND_S" (solid, pour order 938): 27 vertices, not listed, extent -5880,2520 2274.9,3900
GND_S on Layer 1 "Layer 1-GND_S" (solid, pour order 835): 27 vertices, not listed, extent -5880,-3900 2274.9,-2520
S1_S on Layer 1 "Layer 1-S1_S" (solid, pour order 533): 435,-1750 cw(c485.05,-1750.05) 485.05,-1700 624.5,-1700 ccw(c625,-1650) 675,-1650 675,-1545 ccw(c624.95,-1545.05) 625,-1495 380,-1495 ccw(c380.04,-1545.04) 330,-1545 cw(c280,-1545) 280.1,-1595 -160.1,-1595 ccw(c-160,-1645) -210,-1645 -210,-1750.1 ccw(c-160,-1750) -160,-1800 385.1,-1800 ccw(c385,-1750)
S2_S on Layer 1 "Layer 1-S2_S" (solid, pour order 585): 24 vertices, not listed, extent -545,-2485 665,-2005
SA on Layer 1 "Layer 1-SA" (solid, pour order 922): 18 vertices, not listed, extent 450,-2925 2602.5,-1750
SB on Layer 1 "Layer 1-SB" (solid, pour order 909): 17 vertices, not listed, extent 450,-955 2600,-200
PA on Layer 1 "Layer 1-PA" (solid, pour order 908): 22 vertices, not listed, extent 450,200 2599.9,1250
P- on Layer 1 "Layer 1-P-" (solid, pour order 865): 63 vertices, not listed, extent -6200,200 -450,3280
PB on Layer 1 "Layer 1-PB" (solid, pour order 355): 500,2200 2550,2200 ccw(c2549.95,2249.95) 2599.9,2249.9 2600,2875 ccw(c2550,2875) 2550,2925 499.9,2925 ccw(c500,2875) 450,2875 450,2249.9 ccw(c500,2250)
S2_P on Layer 1 "Layer 1-S2_P" (solid, pour order 729): 17 vertices, not listed, extent -585,485 665,805
S4_P on Layer 1 "Layer 1-S4_P" (solid, pour order 667): 17 vertices, not listed, extent -545,2100 215,2485.15
S3_P on Layer 1 "Layer 1-S3_P" (solid, pour order 656): 525.1,1690 ccw(c525,1740) 575,1740 575,2070.1 ccw(c525,2070) 525,2120 489.9,2120 ccw(c490,2070) 440,2070 440,1975 cw(c390,1975) 390.1,1925 -160.1,1925 ccw(c-160,1875) -210,1875 -210,1739.9 ccw(c-160,1740) -160,1690
S1_P on Layer 1 "Layer 1-S1_P" (solid, pour order 632): 17 vertices, not listed, extent -210,990 680,1490
S3_S on Layer 1 "Layer 1-S3_S" (solid, pour order 592): 500.1,-1090 ccw(c500,-1040) 550,-1040 550,-949.9 ccw(c500,-950) 500,-900 -160,-900 ccw(c-160,-950) -210,-949.9 -210,-1040 ccw(c-159.95,-1039.95) -160,-1090
S4_S on Layer 1 "Layer 1-S4_S" (solid, pour order 376): -585,-660 ccw(c-535,-660) -534.98,-710 170.03,-710 ccw(c170,-660) 220,-660.09 220,-569.88 ccw(c170,-570) 170,-520 -535.1,-520 ccw(c-535,-570) -585,-570
S- on Layer 3 "Layer 3-S-" (solid, pour order 826): 69 vertices, not listed, extent -6200,-3280 -450,500
+5V_P on Layer 3 "Layer 1-GND_S" (solid, pour order 941): 27 vertices, not listed, extent -5880,2520 2274.9,3900
+5V_S on Layer 3 "Layer 1-GND_S" (solid, pour order 936): 27 vertices, not listed, extent -5880,-3900 2274.9,-2520
SA on Layer 3 "Layer 3-SA" (solid, pour order 921): 18 vertices, not listed, extent 450,-2925 2602.5,-1750
SB on Layer 3 "Layer 3-SB" (solid, pour order 913): 17 vertices, not listed, extent 450,-955 2600,-200
PA on Layer 3 "Layer 3-PA" (solid, pour order 912): 22 vertices, not listed, extent 450,200 2599.9,1250
PB on Layer 3 "Layer 1-PB" (solid, pour order 906): 500,2200 2550,2200 ccw(c2549.95,2249.95) 2599.9,2249.9 2600,2875 ccw(c2550,2875) 2550,2925 499.9,2925 ccw(c500,2875) 450,2875 450,2249.9 ccw(c500,2250)
P- on Layer 3 "Layer 3-P-" (solid, pour order 882): 69 vertices, not listed, extent -6200,200 -450,3280
GND_P on Layer 4 "Layer 1-GND_S" (solid, pour order 939): 27 vertices, not listed, extent -5880,2520 2274.9,3900
GND_S on Layer 4 "Layer 1-GND_S" (solid, pour order 937): 27 vertices, not listed, extent -5880,-3900 2274.9,-2520
P+ on Layer 4 "Layer 4-P+" (solid, pour order 930): 48 vertices, not listed, extent -6200,200 -450,3280
SA_IO on Layer 4 "Top Layer-SA_IO" (solid, pour order 926): 2600,-2875 cw(c2550,-2875) 2550,-2925 1649.9,-2925 cw(c1650,-2875) 1600,-2875 1600,-1194.9 cw(c1649.95,-1194.95) 1649.9,-1145 2550,-1145 cw(c2549.95,-1195.05) 2600,-1195
SB on Layer 4 "Layer 4-SB" (solid, pour order 915): 17 vertices, not listed, extent 450,-955 2600,-200
PA on Layer 4 "Layer 4-PA" (solid, pour order 914): 22 vertices, not listed, extent 450,200 2599.9,1250
PB_IO on Layer 4 "Top Layer-PB_IO" (solid, pour order 905): 2600,2875 ccw(c2550,2875) 2550,2925 1649.9,2925 ccw(c1650,2875) 1600,2875 1600,1194.9 ccw(c1649.95,1194.95) 1649.9,1145 2550,1145 ccw(c2549.95,1195.05) 2600,1195
S+ on Layer 4 "Layer 4-S+" (solid, pour order 852): 50 vertices, not listed, extent -6200,-3280 -450,500
P-_IO on Layer 4 "Layer 4-P-_IO" (solid, pour order 365): -6200,1195 ccw(c-6149.95,1195.05) -6150,1145 -5684.83,1145 ccw(c-5685,1195) -5635,1195 -5635,1960 cw(c-5585,1960) -5585.1,2010 -5249.9,2010 ccw(c-5250,2060) -5200,2059.83 -5200,2875 ccw(c-5250,2875) -5249.9,2925 -6150,2925 ccw(c-6150,2875) -6200,2875
S-_IO on Layer 4 "Layer 4-S-_IO" (solid, pour order 364): -6200,-1195 cw(c-6149.95,-1195.05) -6150,-1145 -5684.83,-1145 cw(c-5685,-1195) -5635,-1195 -5635,-1960 ccw(c-5585,-1960) -5585.1,-2010 -5249.9,-2010 cw(c-5250,-2060) -5200,-2059.83 -5200,-2875 cw(c-5250,-2875) -5249.9,-2925 -6150,-2925 cw(c-6150,-2875) -6200,-2875
S- on Bottom Layer "Bottom Layer-S-" (solid, pour order 854): 69 vertices, not listed, extent -6200,-3280 -450,500
SA on Bottom Layer "Bottom Layer-SA" (solid, pour order 923): 18 vertices, not listed, extent 450,-2925 2602.5,-1750
SB on Bottom Layer "Bottom Layer-SB" (solid, pour order 917): 17 vertices, not listed, extent 450,-955 2600,-200
PA on Bottom Layer "Bottom Layer-PA" (solid, pour order 916): 22 vertices, not listed, extent 450,200 2599.9,1250
PB on Bottom Layer "Layer 1-PB" (solid, pour order 907): 500,2200 2550,2200 ccw(c2549.95,2249.95) 2599.9,2249.9 2600,2875 ccw(c2550,2875) 2550,2925 499.9,2925 ccw(c500,2875) 450,2875 450,2249.9 ccw(c500,2250)
P- on Bottom Layer "Bottom Layer-P-" (solid, pour order 872): 63 vertices, not listed, extent -6200,200 -450,3280

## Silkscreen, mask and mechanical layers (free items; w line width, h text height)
Top Overlay:
  drawing of 43 lines, arcs and shapes, not listed
  text "IDC-P" at -474.91,2720.01 h60
  text "IDC+P" at 205,2720.01 h60
  text "IAC-P" at -474.91,2620.01 h60
  text "IAC+P" at 205,2620.01 h60
  text "+5VP" at -424.93,2520.01 h60
  text "GNDP" at 205,2520.01 h60
  text "G4P" at -364.95,2120.01 h60
  text "S4P" at 205,2120.01 h60
  text "PB" at -304.97,1820.01 h60
  text "G3P" at 205,1820.01 h60
  text "S3P" at -364.95,1720.01 h60
  text "S3P" at 205,1720.01 h60
  text "P+" at -304.97,1420.01 h60
  text "S1P" at -354.95,1120.01 h60
  text "G1P" at 205,1120.01 h60
  text "P-" at -6080,1060.02 h100
  text "PA" at -304.97,1020.01 h60
  text "S1P" at 205,1020.01 h60
  text "PB" at 2313.39,1010.02 h100
  text "P+" at -6080,865.02 h100
  text "S2P" at -364.95,720.01 h60
  text "NTCP" at 205,720.01 h60
  text "G2P" at -364.95,620.01 h60
  text "P-" at 205,620.01 h60
  text "P+" at -304.97,320.01 h60
  text "P+" at 205,320.01 h60
  text "PA" at 2313.39,210.02 h100
  text "S+" at -304.97,-279.99 h60
  text "S+" at 205,-279.99 h60
  text "SB" at 2313.39,-309.98 h100
  text "S-" at -304.97,-579.99 h60
  text "S4S" at 205,-579.99 h60
  text "S4S" at -364.95,-679.99 h60
  text "G4S" at 205,-679.99 h60
  text "S+" at -6080,-964.98 h100
  text "G3S" at -364.95,-979.99 h60
  text "SB" at 205,-979.99 h60
  text "S3S" at -364.95,-1079.99 h60
  text "S3S" at 205,-1079.99 h60
  text "SA" at 2313.39,-1109.98 h100
  text "S-" at -6080,-1159.98 h100
  text "S+" at -304.97,-1379.99 h60
  text "S+" at 205,-1379.99 h60
  text "S1S" at -354.95,-1679.99 h60
  text "S1S" at 205,-1679.99 h60
  text "SA" at -304.97,-1779.99 h60
  text "G1S" at 205,-1779.99 h60
  text "S2S" at -364.95,-2079.99 h60
  text "G2S" at -364.95,-2179.99 h60
  text "NTCS" at 205,-2179.99 h60
  text "+5VS" at -424.93,-2579.99 h60
  text "GNDS" at 205,-2579.99 h60
  text "IAC-S" at -474.91,-2679.99 h60
  text "IAC+S" at 205,-2679.99 h60
  text "IDC-S" at -474.91,-2779.99 h60
  text "IDC+S" at 205,-2779.99 h60
  text "WOLFPACK 60KW DAB - POWER" at -739.76,-3790 h60
  text "CRD60DD12N-GMB V2.0, 10/2024" at -814.74,-3885.01 h60
Mechanical 1:
  lines w10: -5576.81,-260 -5065,-260 -5065,212.44 -5576.81,212.44 -5576.81,-260
Board Outline:
  the board outline again, w1
Drill Drawing:
  drawing of 181 lines, arcs and shapes, not listed
  text "*" at -6162.5,6512.5 h60
  text "THESE HOLES (1.10MM +/- 0.05MM) ARE FOR PRESS-FIT PART. USE 46.5MIL +/- 1MIL DRILLED HOLES. COPPER THICKNESS IN HOLE 25-50UM." at -6067.5,6457.5 h100
  text "w" at -6293.19,6432.22 h200
  text "^" at -6157.5,6327.51 h60
  text "THESE HOLES (1.48MM +/- 0.05MM) ARE FOR PRESS-FIT PART. USE 63.0MIL +/- 1MIL DRILLED HOLES. COPPER THICKNESS IN HOLE 25-60UM." at -6062.5,6262.5 h100
  text "w" at -6286.65,6244.16 h200
  text "Symbol" at -6202.5,6102.5 h72
  text "Count" at -5696.62,6102.5 h72
  text "Hole Size" at -5096.78,6102.5 h72
  text "Plated" at -3997.1,6102.5 h72
  text "Hole Type" at -3491.23,6102.5 h72
  text "Drill Layer Pair" at -2757.43,6102.5 h72
  text "Via/Pad" at -1257.87,6102.5 h72
  text "Pad Shape" at -668.03,6102.5 h72
  text "Hole Tolerance (+)" at 421.66,6102.5 h72
  text "Hole Tolerance (-)" at 1755.26,6102.5 h72
  text "347" at -5696.62,5952.5 h60
  text "0.33mm (13.00mil)" at -5096.78,5952.5 h60
  text "PTH" at -3997.1,5952.5 h60
  text "Round" at -3491.23,5952.5 h60
  text "Top Layer - Bottom Layer" at -2757.43,5952.5 h60
  text "Via" at -1257.87,5952.5 h60
  text "Rounded" at -668.03,5952.5 h60
  text "0.08mm (3.00mil)" at 421.66,5952.5 h60
  text "0.08mm (3.00mil)" at 1755.26,5952.5 h60
  text "20" at -5696.62,5802.5 h60
  text "0.90mm (35.43mil)" at -5096.78,5802.5 h60
  text "PTH" at -3997.1,5802.5 h60
  text "Round" at -3491.23,5802.5 h60
  text "Top Layer - Bottom Layer" at -2757.43,5802.5 h60
  text "Pad" at -1257.87,5802.5 h60
  text "Rounded" at -668.03,5802.5 h60
  text "0.08mm (3.00mil)" at 421.66,5802.5 h60
  text "0.08mm (3.00mil)" at 1755.26,5802.5 h60
  text "*" at -6367.5,5707.5 h60
  text "68" at -5696.62,5652.5 h60
  text "1.10mm (43.31mil)" at -5096.78,5652.5 h60
  text "PTH" at -3997.1,5652.5 h60
  text "Round" at -3491.23,5652.5 h60
  text "Top Layer - Bottom Layer" at -2757.43,5652.5 h60
  text "Pad" at -1257.87,5652.5 h60
  text "Rounded" at -668.03,5652.5 h60
  text "0.05mm (1.97mil)" at 421.66,5652.5 h60
  text "0.05mm (1.97mil)" at 1755.26,5652.5 h60
  text "w" at -6498.19,5627.22 h200
  text "^" at -6367.5,5557.51 h60
  text "32" at -5696.62,5502.5 h60
  text "1.48mm (58.07mil)" at -5096.78,5502.5 h60
  text "PTH" at -3997.1,5502.5 h60
  text "Round" at -3491.23,5502.5 h60
  text "Top Layer - Bottom Layer" at -2757.43,5502.5 h60
  text "Pad" at -1257.87,5502.5 h60
  text "Rounded" at -668.03,5502.5 h60
  text "0.05mm (1.97mil)" at 421.66,5502.5 h60
  text "0.05mm (1.97mil)" at 1755.26,5502.5 h60
  text "w" at -6496.65,5474.16 h200
  text "16" at -5696.62,5352.5 h60
  text "1.60mm (62.99mil)" at -5096.78,5352.5 h60
  text "PTH" at -3997.1,5352.5 h60
  text "Round" at -3491.23,5352.5 h60
  text "Top Layer - Bottom Layer" at -2757.43,5352.5 h60
  text "Pad" at -1257.87,5352.5 h60
  text "Rounded" at -668.03,5352.5 h60
  text "0.08mm (3.00mil)" at 421.66,5352.5 h60
  text "0.08mm (3.00mil)" at 1755.26,5352.5 h60
  text "4" at -5696.62,5202.5 h60
  text "1.73mm (68.11mil)" at -5096.78,5202.5 h60
  text "NPTH" at -3997.1,5202.5 h60
  text "Round" at -3491.23,5202.5 h60
  text "Top Layer - Bottom Layer" at -2757.43,5202.5 h60
  text "Pad" at -1257.87,5202.5 h60
  text "Rounded" at -668.03,5202.5 h60
  text "0.08mm (3.00mil)" at 421.66,5202.5 h60
  text "0.08mm (3.00mil)" at 1755.26,5202.5 h60
  text "32" at -5696.62,5052.5 h60
  text "2.15mm (84.65mil)" at -5096.78,5052.5 h60
  text "PTH" at -3997.1,5052.5 h60
  text "Round" at -3491.23,5052.5 h60
  text "Top Layer - Bottom Layer" at -2757.43,5052.5 h60
  text "Pad" at -1257.87,5052.5 h60
  text "Rounded" at -668.03,5052.5 h60
  text "0.08mm (3.00mil)" at 421.66,5052.5 h60
  text "0.08mm (3.00mil)" at 1755.26,5052.5 h60
  text "20" at -5696.62,4902.5 h60
  text "2.20mm (86.61mil)" at -5096.78,4902.5 h60
  text "PTH" at -3997.1,4902.5 h60
  text "Round" at -3491.23,4902.5 h60
  text "Top Layer - Bottom Layer" at -2757.43,4902.5 h60
  text "Pad" at -1257.87,4902.5 h60
  text "Rounded" at -668.03,4902.5 h60
  text "0.08mm (3.00mil)" at 421.66,4902.5 h60
  text "0.08mm (3.00mil)" at 1755.26,4902.5 h60
  text "4" at -5696.62,4752.5 h60
  text "4.50mm (177.17mil)" at -5096.78,4752.5 h60
  text "NPTH" at -3997.1,4752.5 h60
  text "Round" at -3491.23,4752.5 h60
  text "Top Layer - Bottom Layer" at -2757.43,4752.5 h60
  text "Pad" at -1257.87,4752.5 h60
  text "Rounded" at -668.03,4752.5 h60
  text "0.13mm (5.00mil)" at 421.66,4752.5 h60
  text "0.13mm (5.00mil)" at 1755.26,4752.5 h60
  text "4" at -5696.62,4602.5 h60
  text "4.50mm (177.17mil)" at -5096.78,4602.5 h60
  text "PTH" at -3997.1,4602.5 h60
  text "Round" at -3491.23,4602.5 h60
  text "Top Layer - Bottom Layer" at -2757.43,4602.5 h60
  text "Pad" at -1257.87,4602.5 h60
  text "Rounded" at -668.03,4602.5 h60
  text "0.13mm (5.00mil)" at 421.66,4602.5 h60
  text "0.13mm (5.00mil)" at 1755.26,4602.5 h60
  text "4" at -5696.62,4452.5 h60
  text "7.06mm (278.00mil)" at -5096.78,4452.5 h60
  text "PTH" at -3997.1,4452.5 h60
  text "Round" at -3491.23,4452.5 h60
  text "Top Layer - Bottom Layer" at -2757.43,4452.5 h60
  text "Pad" at -1257.87,4452.5 h60
  text "Rounded Rectangle" at -668.03,4452.5 h60
  text "0.13mm (5.00mil)" at 421.66,4452.5 h60
  text "0.13mm (5.00mil)" at 1755.26,4452.5 h60
  text "4" at -5696.62,4302.5 h60
  text "9.00mm (354.33mil)" at -5096.78,4302.5 h60
  text "NPTH" at -3997.1,4302.5 h60
  text "Round" at -3491.23,4302.5 h60
  text "Top Layer - Bottom Layer" at -2757.43,4302.5 h60
  text "Pad" at -1257.87,4302.5 h60
  text "Rounded" at -668.03,4302.5 h60
  text "0.13mm (5.00mil)" at 421.66,4302.5 h60
  text "0.13mm (5.00mil)" at 1755.26,4302.5 h60
  text "555 Total" at -5696.62,4152.5 h60

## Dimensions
-6250,-4000 to -6250,4000 on Drill Drawing
-6300,-3950 to 2700,-3950 on Drill Drawing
